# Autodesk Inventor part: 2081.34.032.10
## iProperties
Created: 2012-10
Part Number: 2081.34.032.10
Catalog Web Link: www.cadenas.de
Description: 2081.34. - Headed Guide Bush to DIN 9831/ISO 9448-6, sintered ferrite
Document SubType Name: Modeling
Designer: PARTsolutions
Category: PARTsolutions
Title: 2081.34.032.10
Author: Cadenas PARTsolutions
Comments: Headed Guide Bush to DIN 9831/ISO 9448-6, sintered ferrite
NB: 2081.34.032.10
NN: 2081.34.
NT: Headed Guide Bush to DIN 9831/ISO 9448-6, sintered ferrite
NBSYN: 2081.34.0$D1..$TOL.
LINA: 2081.34.032.10
ROWDESC: 2081.34.032.10
DOC: 2081_34_pdf
D1: 32.000
TOL: 10
D3: 48.000
D4: 48.000
D5: 56.000
D6: 67.000
D7: 79.700
D8: 53.000
A: 24.400
A1: 36.400
L1: 75.000
L2: 30.000
L3: 45.000
K: 3.000
GEW: 0.744
KT: DUMMY
SUPPLIER: FIBRO
ARTICLENO: 2081.34.032.10
BOMINFO: 2081.34.032.10
CREATOR: CADENAS GmbH
PSOL_IDENT_0: {\\10.0.0.251\data_v9\23d-libs\fibro\normalien\d\d05\d05_02\d05_02_01\d05_02_01_04\2081-34.prj},177
PSOL_IDENT_1: {VTYP=3D},{NB=2081.34.032.10},{LINA=2081.34.032.10},{NN=2081.34.},{DATE=10.05.2012 07:32:46},{GEOMDA
PSOL_IDENT_2: TE=16.02.2012 00:00:00},{VERSION=v1},{LINEID=60},{LINESUBID=-1},{WBVAR=TOL}  {NB=2081.34.032.10},{LI
PSOL_IDENT_3: NA=2081.34.032.10},{KT=DUMMY},{DOC=2081_34_pdf},{D1=32.000},{TOL=10},{D3=48.000},{D4=48.000},{D5=56.
PSOL_IDENT_4: 000},{D6=67.000},{D7=79.700},{D8=53.000},{A=24.400},{A1=36.400},{L1=75.000},{L2=30.000},{L3=45.000},
PSOL_IDENT_5: {K=3.000},{GEW=0.743703}
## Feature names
1. Revolution1
2. Extrusion1
3. Extrusion2
4. Extrusion3
5. Extrusion4
6. Extrusion5
7. Extrusion6
8. Extrusion7
9. Extrusion8
10. Extrusion9
11. Extrusion10
12. Extrusion11
13. Extrusion12
14. Extrusion13
15. Extrusion14
16. Extrusion15
